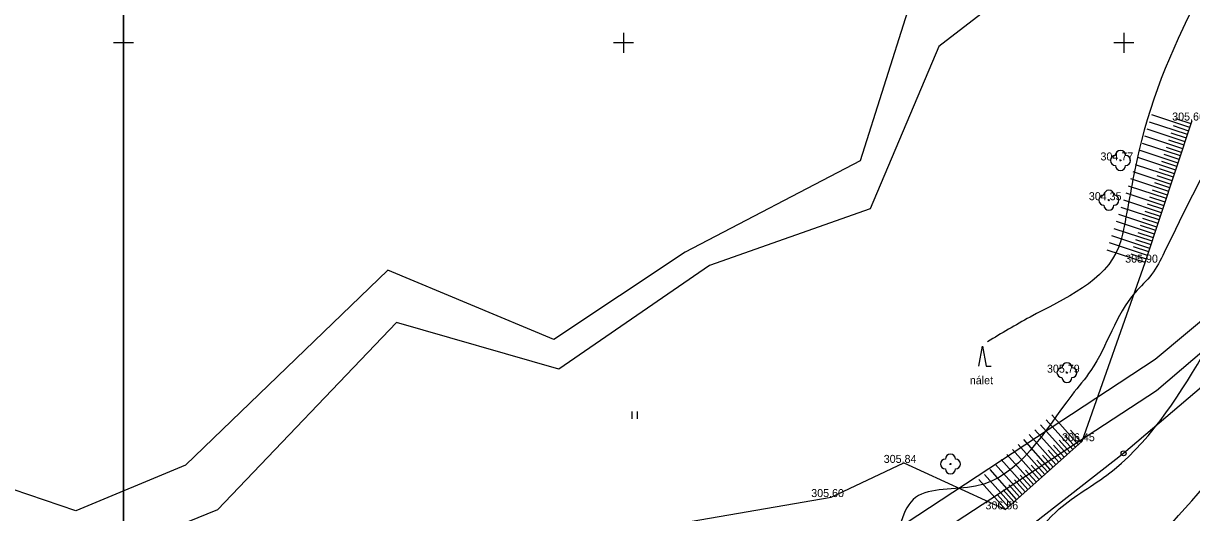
# Model space of a CAD drawing. Extents: x -504375 to -503125, y -1118000 to -1116474.
# Drawn here: x -503760 to -503643.2, y -1117147 to -1117098.1 of the extents above; entities that cross this region are included whole.
import ezdxf

# ---------------------------------------------------------------- set-up
doc = ezdxf.new("R2010")
doc.units = 0
for name, color, linetype in [('Druhy povrchů', 7, 'Continuous'), ('Podkladové mapy', 7, 'Continuous'), ('Stromy a keře', 7, 'Continuous'), ('Síť dekadická', 7, 'Continuous'), ('Vrstva 34', 7, 'Continuous'), ('Vrstva 48', 7, 'Continuous'), ('Výškopis', 7, 'Continuous'), ('Výšky bodů plotr', 7, 'Continuous')]:
    doc.layers.add(name, color=color, linetype=linetype)

msp = doc.modelspace()

# ---------------------------------------------------------------- linework, layer by layer
at = {"layer": 'Druhy povrchů'}
for p, q in [((-503699.127, -1117137.638), (-503699.127, -1117136.888)), ((-503698.627, -1117137.638), (-503698.627, -1117136.888))]:
    msp.add_line(p, q, dxfattribs=at)
msp.add_lwpolyline([(-503664.488, -1117132.369), (-503664.113, -1117130.369), (-503663.738, -1117132.369), (-503663.238, -1117132.369)], dxfattribs=at)
at = {"layer": 'Podkladové mapy'}
for p, q in [((-503654.6, -1117089.64), (-503668.48, -1117100.36)), ((-503671.6, -1117096.86), (-503676.34, -1117111.82)), ((-503668.48, -1117100.36), (-503675.34, -1117116.6)), ((-503676.34, -1117111.82), (-503693.85, -1117120.94)), ((-503675.34, -1117116.6), (-503691.41, -1117122.29)), ((-503646.84, -1117131.67), (-503629.16, -1117116.82)), ((-503628.2, -1117118.94), (-503646.73, -1117134.84)), ((-503693.85, -1117120.94), (-503706.98, -1117129.7)), ((-503723.57, -1117122.76), (-503743.81, -1117142.28)), ((-503706.98, -1117129.7), (-503723.57, -1117122.76)), ((-503691.41, -1117122.29), (-503706.47, -1117132.67)), ((-503722.7, -1117127.99), (-503740.61, -1117146.74)), ((-503706.47, -1117132.67), (-503722.7, -1117127.99)), ((-503698.26, -1117165.42), (-503646.84, -1117131.67)), ((-503646.73, -1117134.84), (-503696.12, -1117167.1)), ((-503650.01, -1117141.08), (-503642.21, -1117134.44)), ((-503696.57, -1117177.3), (-503650.01, -1117141.08)), ((-503754.76, -1117146.84), (-503766.06, -1117143.02)), ((-503743.81, -1117142.28), (-503754.76, -1117146.84)), ((-503740.61, -1117146.74), (-503754.67, -1117152.43))]:
    msp.add_line(p, q, dxfattribs=at)
for radius in [0.25, 0.005]:
    msp.add_circle((-503650.01, -1117141.08), radius, dxfattribs=at)
at = {"layer": 'Stromy a keře'}
for centre in [(-503650.32, -1117111.77), (-503651.48, -1117115.75), (-503655.67, -1117133.01), (-503667.32, -1117142.15)]:
    msp.add_circle(centre, 0.05, dxfattribs=at)
for centre, start, end in [((-503650.82, -1117111.77), 90, 270), ((-503650.32, -1117111.27), 0, 180), ((-503649.82, -1117111.77), 270, 90), ((-503650.32, -1117112.27), 180, 0), ((-503651.48, -1117115.25), 0, 180), ((-503651.98, -1117115.75), 90, 270), ((-503650.98, -1117115.75), 270, 90), ((-503651.48, -1117116.25), 180, 0), ((-503656.17, -1117133.01), 90, 270), ((-503655.67, -1117132.51), 0, 180), ((-503655.17, -1117133.01), 270, 90), ((-503655.67, -1117133.51), 180, 0), ((-503667.82, -1117142.15), 90, 270), ((-503667.32, -1117141.65), 0, 180), ((-503666.82, -1117142.15), 270, 90), ((-503667.32, -1117142.65), 180, 0)]:
    msp.add_arc(centre, 0.5, start, end, dxfattribs=at)
at = {"layer": 'Síť dekadická'}
for points in [[(-503750, -1117000), (-503750, -1117500), (-504375, -1117500), (-504375, -1117000)], [(-503125, -1117000), (-503125, -1117500), (-503750, -1117500), (-503750, -1117000)]]:
    msp.add_lwpolyline(points, close=True, dxfattribs=at)
at = {"layer": 'Vrstva 34'}
for p, q in [((-503750, -1117099), (-503750, -1117101)), ((-503700, -1117099), (-503700, -1117101)), ((-503650, -1117099), (-503650, -1117101)), ((-503749, -1117100), (-503751, -1117100)), ((-503699, -1117100), (-503701, -1117100)), ((-503649, -1117100), (-503651, -1117100))]:
    msp.add_line(p, q, dxfattribs=at)
msp.add_lwpolyline([(-503750, -1116754.229), (-503750, -1117230.829)], dxfattribs=at)
at = {"layer": 'Vrstva 48'}
for points in [[(-503583.436, -1116916.735), (-503565.222, -1116898.002), (-503545.734, -1116881.633), (-503534.572, -1116870.778), (-503513.205, -1116846.809), (-503510.867, -1116843.732), (-503510.418, -1116843.732), (-503511.603, -1116846.232), (-503518.586, -1116862.77), (-503523.84, -1116880.397), (-503523.84, -1116881.294), (-503515.357, -1116898.665), (-503516.275, -1116901.249), (-503527.394, -1116929.845), (-503527.394, -1116936.169), (-503527.485, -1116936.022), (-503531.377, -1116947.63), (-503532.293, -1116950.302), (-503533.896, -1116960.764), (-503542.598, -1116970.081), (-503552.37, -1116992.445), (-503555.496, -1116996.72), (-503562.532, -1117003.134), (-503574.935, -1117012.154), (-503576.446, -1117014.604), (-503591.634, -1117036.568), (-503596.086, -1117041.635), (-503600.171, -1117047.806), (-503611.566, -1117069.423), (-503612.057, -1117071.221), (-503614.181, -1117072.938), (-503624.76, -1117093.42), (-503637.766, -1117106.652), (-503639.522, -1117109.013), (-503645.943, -1117120.982), (-503647.205, -1117123.178), (-503648.851, -1117124.99), (-503653.281, -1117132.788), (-503655.18, -1117135.25), (-503664.808, -1117144.375), (-503670.8, -1117145.499), (-503672.957, -1117151.15), (-503675.518, -1117162.241), (-503680.888, -1117175.407), (-503686.593, -1117176.265), (-503690.913, -1117183.112)], [(-503681.581, -1117189.358), (-503677.862, -1117181.382), (-503666.722, -1117185.997), (-503660.312, -1117176.769), (-503662.273, -1117171.205), (-503665.544, -1117166.288), (-503664.496, -1117159.63), (-503663.424, -1117157.82), (-503656.724, -1117146.894), (-503651.699, -1117143.274), (-503642.136, -1117131.351), (-503640.456, -1117128.532), (-503633.339, -1117117.852), (-503629.848, -1117112.023), (-503622.694, -1117102.978), (-503617.219, -1117095.012), (-503609.076, -1117080.347), (-503600.768, -1117066.026), (-503593.131, -1117053.049), (-503583.142, -1117034.879)], [(-503670.377, -1117191.619), (-503669.68, -1117189.038), (-503667.476, -1117187.838), (-503659.224, -1117178.665), (-503659.729, -1117171.664), (-503658.467, -1117166.241), (-503646.499, -1117149.509), (-503636.524, -1117137.367), (-503628.369, -1117122.514), (-503620.153, -1117109.423), (-503610.19, -1117096.668), (-503601.485, -1117082.212), (-503593.478, -1117067.759), (-503585.924, -1117054.445), (-503581.971, -1117047.028)], [(-503663.774, -1117189.171), (-503657.669, -1117182.299), (-503653.803, -1117173.825), (-503650.734, -1117168.851), (-503649.206, -1117166.706), (-503639.945, -1117154.236), (-503631.523, -1117142.215), (-503623.535, -1117130.705), (-503616.437, -1117119.955), (-503611.15, -1117107.935), (-503600.425, -1117091.261), (-503593.212, -1117078.753), (-503585.366, -1117064.793), (-503579.769, -1117055.757)], [(-503632.866, -1117079.324), (-503648.483, -1117110.842), (-503649.96, -1117118.382), (-503650.49, -1117120.413), (-503659.36, -1117127.451), (-503663.602, -1117129.909)]]:
    msp.add_spline(points, degree=3, dxfattribs=at)
at = {"layer": 'Výškopis'}
for p, q in [((-503643.613, -1117109.182), (-503647.411, -1117107.927)), ((-503643.378, -1117108.47), (-503647.176, -1117107.215)), ((-503643.26, -1117108.114), (-503644.78, -1117107.612)), ((-503643.849, -1117109.894), (-503647.647, -1117108.639)), ((-503643.731, -1117109.538), (-503645.25, -1117109.036)), ((-503643.496, -1117108.826), (-503645.015, -1117108.324)), ((-503644.319, -1117111.318), (-503648.117, -1117110.063)), ((-503644.084, -1117110.606), (-503647.882, -1117109.351)), ((-503643.966, -1117110.25), (-503645.486, -1117109.748)), ((-503644.79, -1117112.743), (-503648.588, -1117111.487)), ((-503644.555, -1117112.03), (-503648.353, -1117110.775)), ((-503644.437, -1117111.674), (-503645.956, -1117111.172)), ((-503644.202, -1117110.962), (-503645.721, -1117110.46)), ((-503645.026, -1117113.455), (-503648.824, -1117112.199)), ((-503644.908, -1117113.099), (-503646.427, -1117112.596)), ((-503644.673, -1117112.386), (-503646.192, -1117111.884)), ((-503645.496, -1117114.879), (-503649.294, -1117113.624)), ((-503645.261, -1117114.167), (-503649.059, -1117112.911)), ((-503645.143, -1117113.811), (-503646.662, -1117113.309)), ((-503645.732, -1117115.591), (-503649.53, -1117114.336)), ((-503645.614, -1117115.235), (-503647.133, -1117114.733)), ((-503645.379, -1117114.523), (-503646.898, -1117114.021)), ((-503646.202, -1117117.015), (-503650, -1117115.76)), ((-503645.967, -1117116.303), (-503649.765, -1117115.048)), ((-503646.085, -1117116.659), (-503647.604, -1117116.157)), ((-503645.849, -1117115.947), (-503647.369, -1117115.445)), ((-503646.673, -1117118.439), (-503650.471, -1117117.184)), ((-503646.438, -1117117.727), (-503650.236, -1117116.472)), ((-503646.32, -1117117.371), (-503647.839, -1117116.869)), ((-503646.909, -1117119.152), (-503650.706, -1117117.896)), ((-503646.791, -1117118.795), (-503648.31, -1117118.293)), ((-503646.555, -1117118.083), (-503648.075, -1117117.581)), ((-503647.379, -1117120.576), (-503651.177, -1117119.32)), ((-503647.144, -1117119.864), (-503650.942, -1117118.608)), ((-503647.026, -1117119.508), (-503648.545, -1117119.005)), ((-503647.85, -1117122), (-503651.648, -1117120.745)), ((-503647.615, -1117121.288), (-503651.413, -1117120.033)), ((-503647.497, -1117120.932), (-503649.016, -1117120.43)), ((-503647.262, -1117120.22), (-503648.781, -1117119.718)), ((-503647.732, -1117121.644), (-503649.251, -1117121.142)), ((-503655.658, -1117141.204), (-503658.318, -1117138.217)), ((-503655.098, -1117140.705), (-503657.758, -1117137.718)), ((-503654.538, -1117140.207), (-503657.198, -1117137.219)), ((-503656.779, -1117142.201), (-503659.438, -1117139.214)), ((-503656.218, -1117141.703), (-503658.878, -1117138.715)), ((-503654.818, -1117140.456), (-503655.882, -1117139.261)), ((-503654.258, -1117139.957), (-503655.322, -1117138.762)), ((-503657.899, -1117143.199), (-503660.559, -1117140.211)), ((-503657.339, -1117142.7), (-503659.999, -1117139.713)), ((-503655.938, -1117141.453), (-503657.002, -1117140.258)), ((-503655.378, -1117140.955), (-503656.442, -1117139.76)), ((-503659.579, -1117144.695), (-503662.239, -1117141.708)), ((-503659.019, -1117144.196), (-503661.679, -1117141.209)), ((-503658.459, -1117143.698), (-503661.119, -1117140.71)), ((-503657.619, -1117142.95), (-503658.683, -1117141.755)), ((-503657.059, -1117142.451), (-503658.123, -1117141.256)), ((-503656.499, -1117141.952), (-503657.562, -1117140.757)), ((-503660.7, -1117145.693), (-503663.36, -1117142.705)), ((-503660.14, -1117145.194), (-503662.799, -1117142.206)), ((-503658.739, -1117143.947), (-503659.803, -1117142.752)), ((-503658.179, -1117143.448), (-503659.243, -1117142.253)), ((-503661.82, -1117146.69), (-503664.48, -1117143.703)), ((-503661.26, -1117146.191), (-503663.92, -1117143.204)), ((-503659.859, -1117144.944), (-503660.923, -1117143.749)), ((-503659.299, -1117144.446), (-503660.363, -1117143.251)), ((-503661.54, -1117146.441), (-503662.604, -1117145.246)), ((-503660.98, -1117145.942), (-503662.044, -1117144.747)), ((-503660.42, -1117145.443), (-503661.484, -1117144.248))]:
    msp.add_line(p, q, dxfattribs=at)
for points in [[(-503647.85, -1117122), (-503643.15, -1117107.78)], [(-503654.16, -1117139.87), (-503647.85, -1117122)], [(-503661.82, -1117146.69), (-503654.16, -1117139.87)], [(-503722.83, -1117176.18), (-503720.95, -1117173.44), (-503717.91, -1117166.76), (-503708.68, -1117156.65), (-503696.04, -1117148.36), (-503679.24, -1117145.46), (-503671.99, -1117142.04), (-503661.82, -1117146.69)]]:
    msp.add_lwpolyline(points, dxfattribs=at)

# ---------------------------------------------------------------- texts
at = {"layer": 'Druhy povrchů'}
msp.add_text('nálet', height=0.8, dxfattribs=at).set_placement((-503665.383, -1117134.166))
at = {"layer": 'Výšky bodů plotr'}
for s, p in [('305.66 ', (-503645.15, -1117107.78)), ('304.77 ', (-503652.32, -1117111.77)), ('304.35 ', (-503653.48, -1117115.75)), ('305.90 ', (-503649.85, -1117122)), ('305.79 ', (-503657.67, -1117133.01)), ('306.45 ', (-503656.16, -1117139.87)), ('305.84 ', (-503673.99, -1117142.04)), ('305.60 ', (-503681.24, -1117145.46)), ('306.56 ', (-503663.82, -1117146.69))]:
    msp.add_text(s, height=0.8, dxfattribs=at).set_placement(p)

doc.saveas('drawing.dxf')
